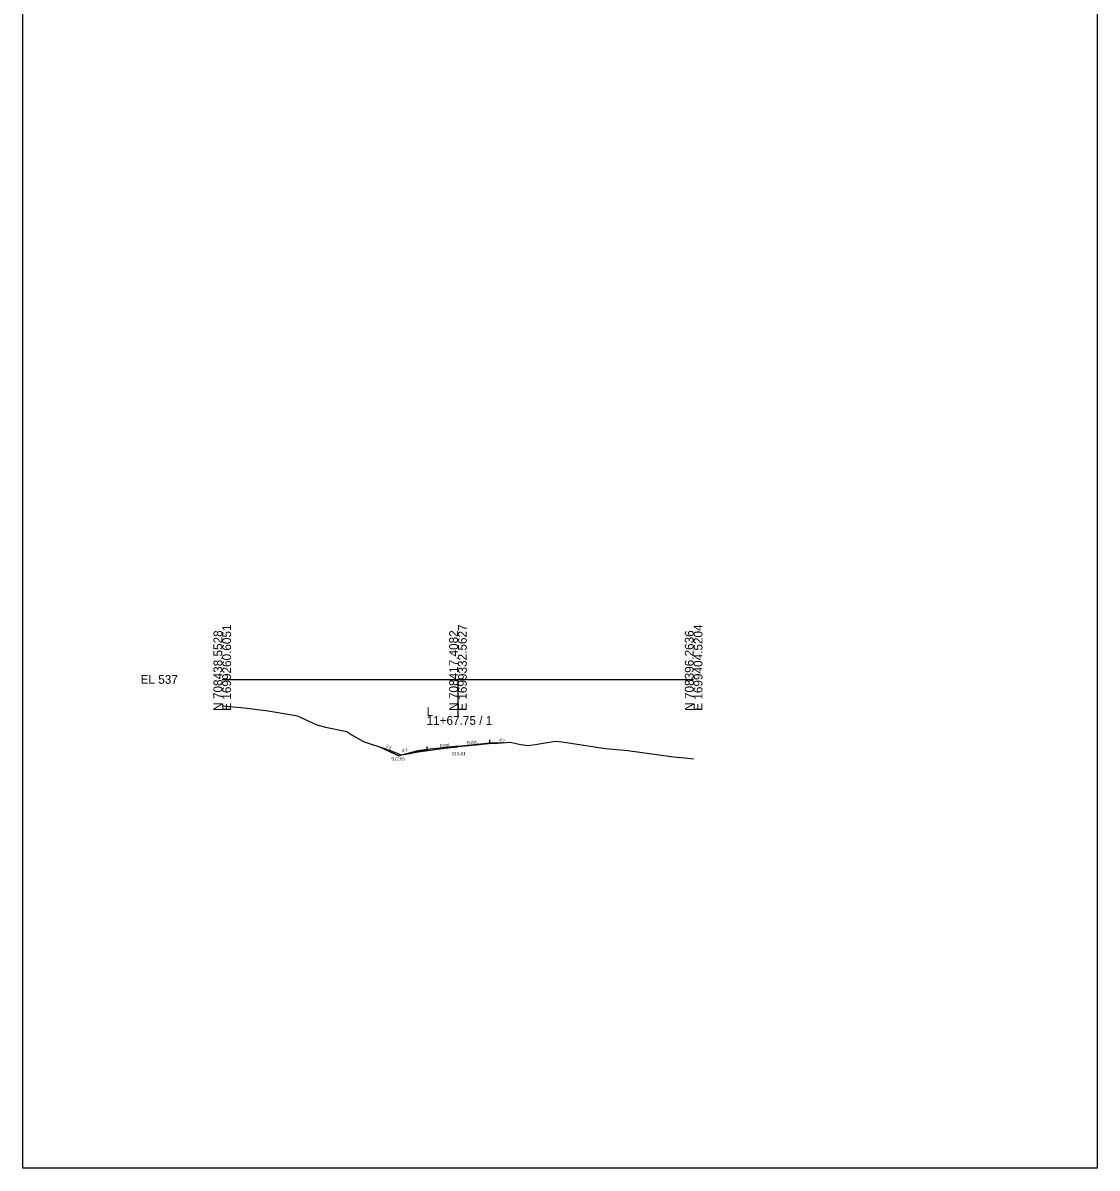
# Model space of a CAD drawing. Extents: x -63 to 1153, y -24 to 9522.
# Drawn here: x -63.4 to 278.4, y 844.5 to 1208.9 of the extents above; entities that cross this region are included whole.
import ezdxf

# ---------------------------------------------------------------- set-up
doc = ezdxf.new("R2010")
doc.units = 0
for name, color, linetype in [('Default', 7, 'Continuous'), ('Exist Cross Section Cell', 7, 'Continuous'), ('Exist XS Center Line Elevation Label', 7, 'Continuous'), ('Exist XS Ground Line', 7, 'Continuous'), ('Prop CMT DNC', 7, 'Continuous'), ('Prop CMT Pvmt Surface Overlay', 7, 'Continuous'), ('Prop CMT Slope Grass', 7, 'Continuous'), ('Prop XS Ditch Standard Text', 7, 'Continuous'), ('Prop XS Earthwork Shape', 7, 'Continuous'), ('Prop XS EOT Tick Mark', 7, 'Continuous'), ('Prop XS SE Text', 7, 'Continuous'), ('Prop XS Side Slope Text', 7, 'Continuous')]:
    doc.layers.add(name, color=color, linetype=linetype)

msp = doc.modelspace()

# ---------------------------------------------------------------- linework, layer by layer
at = {"layer": 'Exist Cross Section Cell'}
for p, q in [((0, 1000), (75, 1000)), ((75, 1000), (150, 1000)), ((75, 1000), (75, 988.34))]:
    msp.add_line(p, q, dxfattribs=at)
at = {"layer": 'Exist XS Ground Line'}
msp.add_lwpolyline([(0, 991.59), (7.05, 991), (14.65, 990.03), (23.41, 988.56), (24.13, 988.33), (24.75, 988.03), (30.09, 985.55), (32.85, 984.8), (39.62, 983.41), (41.53, 982.16), (44.75, 980.34), (45.45, 980.02), (51.62, 978), (51.93, 977.9), (51.99, 977.88), (54.31, 977.07), (56.93, 975.99), (58.46, 976.23), (60.15, 976.57), (62.36, 976.95), (64.71, 977.31), (70.76, 978.08), (74.88, 978.59), (75, 978.61), (80.81, 979.15), (84.75, 979.55), (87.63, 979.68), (90.3, 979.87), (91.72, 979.98), (93.54, 979.63), (95, 979.32), (96.46, 979.09), (97.48, 978.96), (100.21, 979.4), (105.99, 980.3), (108.17, 980.13), (108.75, 980), (121.98, 978.01), (129.02, 977.36), (142.8, 975.49), (144.55, 975.23), (146.06, 975.12), (148.15, 974.9), (150, 974.71)], dxfattribs=at)
at = {"layer": 'Prop CMT DNC'}
msp.add_lwpolyline([(-63.45, 1573.23), (278.38, 1573.23), (278.38, 844.51), (-63.45, 844.51)], close=True, dxfattribs=at)
at = {"layer": 'Prop CMT Pvmt Surface Overlay'}
msp.add_line((75.2, 978.76), (85.18, 979.8), dxfattribs=at)
msp.add_lwpolyline([(75.2, 978.76), (65.22, 977.64)], dxfattribs=at)
at = {"layer": 'Prop CMT Slope Grass'}
for p, q in [((62.23, 977.3), (56.18, 975.65)), ((65.21, 977.64), (65.21, 977.37)), ((85.19, 979.8), (85.2, 979.57)), ((88.18, 979.94), (88.86, 979.77))]:
    msp.add_line(p, q, dxfattribs=at)
for points in [[(50.29, 978.43), (56.18, 975.65)], [(65.21, 977.64), (62.23, 977.3)], [(85.19, 979.8), (88.18, 979.94)]]:
    msp.add_lwpolyline(points, dxfattribs=at)
at = {"layer": 'Prop XS Earthwork Shape'}
for points in [[(56.93, 975.99), (58.1, 976.18), (56.18, 975.65), (50.29, 978.43), (51.62, 978), (51.93, 977.9), (51.99, 977.88), (54.31, 977.07)], [(65.21, 977.64), (65.21, 977.37), (64.71, 977.31), (62.36, 976.95), (60.15, 976.57), (58.46, 976.23), (58.1, 976.18), (62.23, 977.3)], [(85.19, 979.8), (88.18, 979.94), (88.86, 979.77), (87.63, 979.68), (85.2, 979.57)]]:
    msp.add_lwpolyline(points, close=True, dxfattribs=at)
at = {"layer": 'Prop XS EOT Tick Mark'}
for points in [[(85.18, 979.8), (85.17, 980.8)], [(65.22, 977.64), (65.2, 978.64)]]:
    msp.add_lwpolyline(points, dxfattribs=at)

# ---------------------------------------------------------------- texts
at = {"layer": 'Default'}
msp.add_text('-', height=0.0001, dxfattribs=at).set_placement((0, 1000))
msp.add_text('-', height=0.0001, dxfattribs=at).set_placement((0, 1000))
at = {"layer": 'Exist Cross Section Cell'}
for s, p in [('E 1699260.6051', (2.8, 990)), ('E 1699332.5627', (77.8, 990)), ('E 1699404.5204', (152.8, 990)), ('N 708438.5528', (0, 990)), ('N 708417.4082', (75, 990)), ('N 708396.2636', (150, 990))]:
    msp.add_text(s, height=2.8, rotation=90, dxfattribs=at).set_placement(p)
for s, p in [('EL 537', (-26, 998.6)), ('L', (65, 988.34)), ('11+67.75 / 1', (65, 985.54))]:
    msp.add_text(s, height=2.8, dxfattribs=at).set_placement(p)
at = {"layer": 'Exist XS Center Line Elevation Label'}
msp.add_text('515.61', height=1, dxfattribs=at).set_placement((73.16, 975.86))
at = {"layer": 'Prop XS Ditch Standard Text'}
msp.add_text('512.65', height=1, dxfattribs=at).set_placement((53.84, 974.24))
at = {"layer": 'Prop XS SE Text'}
for p in [(77.99, 979.34), (69.32, 978.41)]:
    msp.add_text('Exist.', height=1, rotation=6.4909, dxfattribs=at).set_placement(p)
at = {"layer": 'Prop XS Side Slope Text'}
for s, rotation, p in [('4:1', 340.5124, (87.98, 980.44)), ('2:1', 333.4327, (51.91, 978.45)), ('4:1', 14.0363, (57.25, 976.82))]:
    msp.add_text(s, height=1, rotation=rotation, dxfattribs=at).set_placement(p)

doc.saveas('drawing.dxf')
